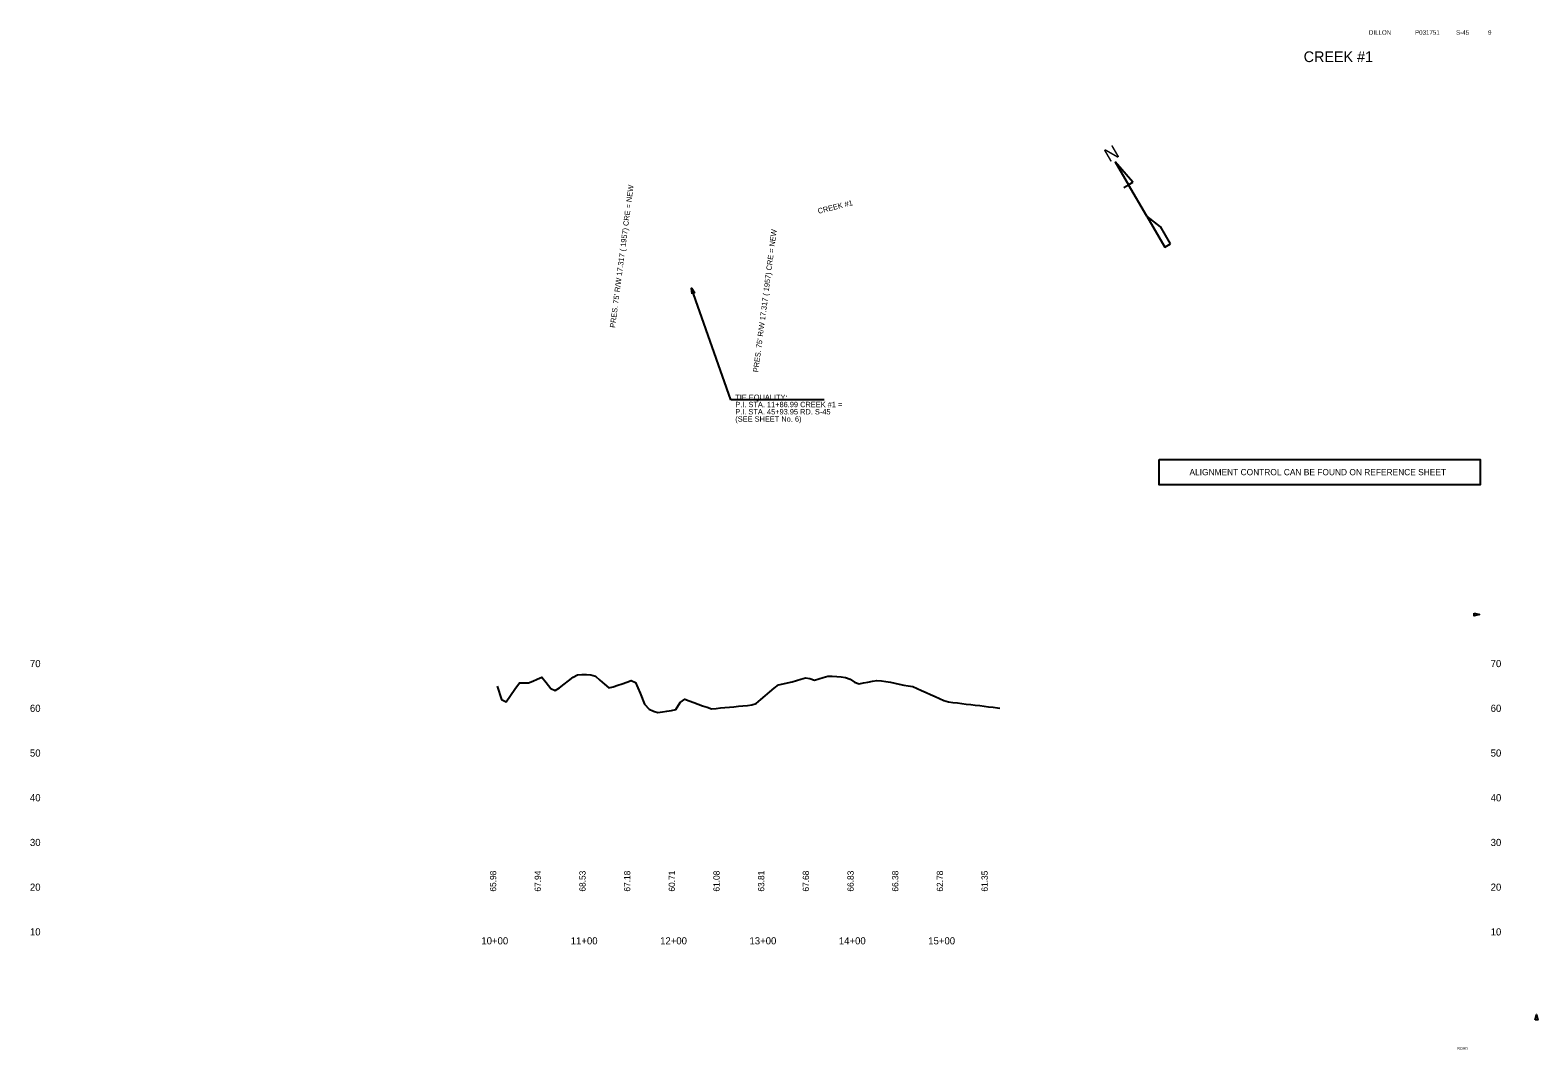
# Model space of a CAD drawing. Extents: x -3336 to 3318, y -3606 to 6276.
# Drawn here: x -72 to 1615, y 2823 to 3963 of the extents above; entities that cross this region are included whole.
import ezdxf

# ---------------------------------------------------------------- set-up
doc = ezdxf.new("R2010")
doc.units = 0
for name, color, linetype in [('RD_DDB_ElevTX', 7, 'Continuous'), ('RD_DDB_Profile_EX', 7, 'Continuous'), ('RD_DDB_StaTX', 7, 'Continuous'), ('RD_DDB_StripGrade', 7, 'Continuous'), ('RD_EX_Misc', 7, 'Continuous'), ('RD_EX_RW_TX', 7, 'Continuous'), ('RD_HC_Data', 7, 'Continuous'), ('RD_SHT_TX', 7, 'Continuous'), ('RD_Sketch1', 7, 'Continuous'), ('RD_TX_Drainage', 7, 'Continuous'), ('RD_TX_RoadID', 7, 'Continuous')]:
    doc.layers.add(name, color=color, linetype=linetype)

msp = doc.modelspace()

# ---------------------------------------------------------------- linework, layer by layer
at = {"layer": 'RD_DDB_Profile_EX'}
for points in [[(450, 3229.9), (455, 3214.9), (460, 3212.4), (465, 3219.4), (470, 3226.4), (475, 3233.5), (480, 3233.4), (485, 3233.5), (490, 3235.5), (495, 3237.6), (500, 3239.7), (505, 3233.7), (510, 3227.1), (515, 3224.8), (520, 3227.8), (525, 3231.8), (530, 3235.8), (535, 3239.8), (540, 3242.5), (545, 3242.7), (550, 3242.7), (555, 3242.4), (560, 3241.1), (565, 3236.6), (570, 3232.1), (575, 3227.7), (580, 3228.9), (585, 3230.7), (590, 3232.4), (595, 3234.2), (600, 3235.9), (605, 3233.9), (610, 3221.8), (615, 3209.7), (620, 3204.2), (625, 3201.7), (630, 3200.2), (635, 3201), (640, 3201.9), (645, 3202.7), (650, 3203.5), (655, 3211.4), (660, 3215.2), (665, 3213.4), (670, 3211.6), (675, 3209.7), (680, 3207.9), (685, 3206.1), (690, 3204.4), (695, 3204.9), (700, 3205.4), (705, 3205.9), (710, 3206.4), (715, 3206.8), (720, 3207.3), (725, 3207.8), (730, 3208.3), (735, 3208.8), (740, 3210.5), (745, 3214.7), (750, 3219), (755, 3223.3), (760, 3227.6), (765, 3231.2), (770, 3232.4), (775, 3233.5), (780, 3234.7), (785, 3236.2), (790, 3237.7), (795, 3239.2), (800, 3238.4), (805, 3236.6), (810, 3238), (815, 3239.4), (820, 3240.8), (825, 3241.1), (830, 3240.6), (835, 3240.2), (840, 3239.5), (845, 3237.6), (850, 3234.2), (855, 3232.4), (860, 3233.4), (865, 3234.3), (870, 3235.2), (875, 3236), (880, 3235.8), (885, 3235), (890, 3234.1), (895, 3233), (900, 3231.9), (905, 3230.8), (910, 3230), (915, 3229.3), (920, 3227.2), (925, 3225), (930, 3222.8), (935, 3220.5), (940, 3218.3), (945, 3216.1), (950, 3213.9)], [(950, 3213.9), (955, 3212.2), (960, 3211.6), (965, 3211), (970, 3210.4), (975, 3209.8), (980, 3209.2), (985, 3208.6), (990, 3208), (995, 3207.3), (1000, 3206.7), (1005, 3206.1), (1010, 3205.5), (1012.4, 3205.2)]]:
    msp.add_lwpolyline(points, dxfattribs=at)
at = {"layer": 'RD_EX_Misc'}
for p, q in [((1161.5, 3793.4), (1141.6, 3815.9)), ((1141.6, 3815.9), (1141.6, 3815.9)), ((1141.6, 3815.9), (1156.4, 3790.5)), ((1151.3, 3787.5), (1156.4, 3790.5)), ((1156.4, 3790.5), (1161.5, 3793.4)), ((1176.9, 3755.2), (1156.4, 3790.5)), ((1161.5, 3793.4), (1161.3, 3793.7)), ((1192.4, 3743.4), (1176.9, 3755.2)), ((1176.9, 3755.2), (1197.1, 3720.6)), ((1203.5, 3724.3), (1192.3, 3743.6)), ((1192.3, 3743.6), (1192.4, 3743.4)), ((1197.1, 3720.6), (1203.5, 3724.3))]:
    msp.add_line(p, q, dxfattribs=at)
at = {"layer": 'RD_HC_Data'}
for p, q in [((711.5, 3549.8), (667.6, 3674.8)), ((816, 3549.8), (711.5, 3549.8))]:
    msp.add_line(p, q, dxfattribs=at)
at = {"layer": 'RD_Sketch1'}
msp.add_lwpolyline([(1190.8, 3483.3), (1550, 3483.3), (1550, 3454.9), (1190.8, 3454.9)], close=True, dxfattribs=at)
at = {"layer": 'RD_TX_Drainage'}
for points in [[(668.2, 3668.6), (667.6, 3674.8), (671, 3669.6)], [(1543.3, 3311.5), (1549.3, 3310), (1543.3, 3308.5)], [(1611.5, 2856.5), (1613, 2862.5), (1614.5, 2856.5)]]:
    msp.add_lwpolyline(points, close=True, dxfattribs=at)

# ---------------------------------------------------------------- texts
at = {"layer": 'RD_DDB_ElevTX'}
for s, p in [('70', (-72.7, 3251)), ('70', (1561.7, 3251)), ('60', (-72.7, 3201)), ('60', (1561.7, 3201)), ('50', (-72.7, 3151)), ('50', (1561.7, 3151)), ('40', (-72.7, 3101)), ('40', (1561.7, 3101)), ('30', (-72.7, 3051)), ('30', (1561.7, 3051)), ('20', (-72.7, 3001)), ('20', (1561.7, 3001)), ('10', (-72.7, 2951)), ('10', (1561.7, 2951))]:
    msp.add_text(s, height=8, dxfattribs=at).set_placement(p)
at = {"layer": 'RD_DDB_StaTX'}
for s, p in [('10+00', (432.4, 2941)), ('11+00', (532.4, 2941)), ('12+00', (632.4, 2941)), ('13+00', (732.4, 2941)), ('14+00', (832.4, 2941)), ('15+00', (932.4, 2941))]:
    msp.add_text(s, height=8, dxfattribs=at).set_placement(p)
at = {"layer": 'RD_DDB_StripGrade'}
for s, p in [('65.98', (449, 3000)), ('67.94', (499, 3000)), ('68.53', (549, 3000)), ('67.18', (599, 3000)), ('60.71', (649, 3000)), ('61.08', (699, 3000)), ('63.81', (749, 3000)), ('67.68', (799, 3000)), ('66.83', (849, 3000)), ('66.38', (899, 3000)), ('62.78', (949, 3000)), ('61.35', (999, 3000))]:
    msp.add_text(s, height=7, rotation=90, dxfattribs=at).set_placement(p)
at = {"layer": 'RD_EX_Misc'}
msp.add_text('N', height=15, rotation=30.2681, dxfattribs=at).set_placement((1135, 3815.3))
at = {"layer": 'RD_EX_RW_TX'}
for p in [(582, 3630.1), (742.2, 3580.4)]:
    msp.add_text("PRES. 75' R/W 17.317 ( 1957) CRE = NEW", height=6, rotation=82.5949, dxfattribs=at).set_placement(p)
at = {"layer": 'RD_HC_Data'}
for s, p in [('TIE EQUALITY:', (716.5, 3549.8)), ('P.I. STA. 11+86.99 CREEK #1 =', (716.5, 3541.7)), ('(SEE SHEET No. 6)', (716.5, 3525.5)), ('P.I. STA. 45+93.95 RD. S-45', (716.5, 3533.6))]:
    msp.add_text(s, height=6, dxfattribs=at).set_placement(p)
at = {"layer": 'RD_SHT_TX'}
for s, height, p in [('DILLON', 5, (1425.5, 3958.2)), ('P031751', 5, (1477.1, 3958.2)), ('S-45', 5, (1523, 3958.2)), ('9', 5, (1558.8, 3958.2)), ('CREEK #1', 12, (1352.5, 3927.6)), ('ROAD', 3, (1524.3, 2823.1))]:
    msp.add_text(s, height=height, dxfattribs=at).set_placement(p)
at = {"layer": 'RD_Sketch1'}
msp.add_text('ALIGNMENT CONTROL CAN BE FOUND ON REFERENCE SHEET', height=7, dxfattribs=at).set_placement((1224.7, 3465.6))
at = {"layer": 'RD_TX_RoadID'}
msp.add_text('CREEK #1', height=6, rotation=14.0833, dxfattribs=at).set_placement((809.6, 3757.9))

doc.saveas('drawing.dxf')
